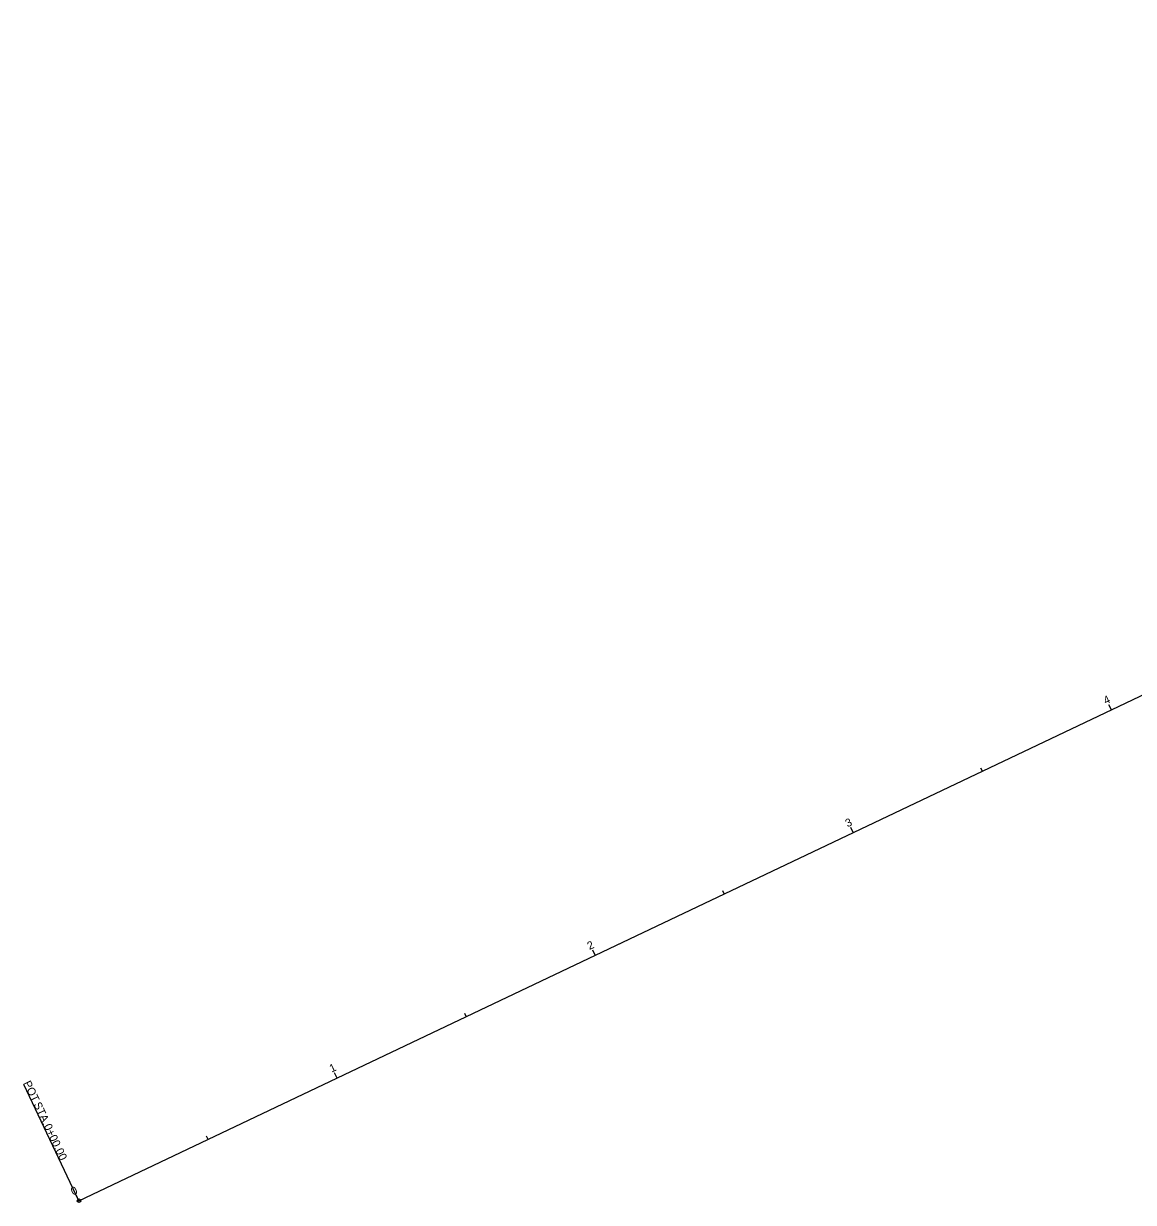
# Model space of a CAD drawing. Extents: x 219353 to 221640, y 361458 to 364236.
# Drawn here: x 219352.5 to 219740.9, y 361639.9 to 362052.3 of the extents above; entities that cross this region are included whole.
import ezdxf

# ---------------------------------------------------------------- set-up
doc = ezdxf.new("R2010")
doc.units = 0
for name, color, linetype in [('DR_X_Cells', 7, 'Continuous'), ('DT_X_Contour_Major', 7, 'Continuous'), ('SC_ProfileRun2', 7, 'Continuous'), ('SC_ProfileRun3', 7, 'Continuous'), ('UT_X_Sanitary_Cells', 7, 'Continuous')]:
    doc.layers.add(name, color=color, linetype=linetype)

msp = doc.modelspace()

# ---------------------------------------------------------------- linework, layer by layer
at = {"layer": 'DR_X_Cells'}
msp.add_line((219371.89, 361640.54), (219352.58, 361681.19), dxfattribs=at)
msp.add_circle((219371.89, 361640.54), 0.6, dxfattribs=at)
at = {"layer": 'DT_X_Contour_Major'}
msp.add_line((219371.89, 361640.54), (220238.34, 362052.3), dxfattribs=at)
msp.add_line((219371.89, 361640.54), (220238.34, 362052.3), dxfattribs=at)
at = {"layer": 'SC_ProfileRun2'}
msp.add_line((219371.89, 361640.54), (219352.58, 361681.19), dxfattribs=at)
msp.add_circle((219371.89, 361640.54), 0.6, dxfattribs=at)
at = {"layer": 'SC_ProfileRun3'}
for p, q in [((219733.17, 361812.23), (219732.66, 361813.32)), ((219642.85, 361769.31), (219642.34, 361770.39)), ((219552.53, 361726.39), (219552.02, 361727.47)), ((219462.21, 361683.46), (219461.7, 361684.55)), ((219371.89, 361640.54), (219371.04, 361642.35))]:
    msp.add_line(p, q, dxfattribs=at)
at = {"layer": 'UT_X_Sanitary_Cells'}
for p, q in [((219733.17, 361812.23), (219732.31, 361814.04)), ((219688.01, 361790.77), (219687.5, 361791.85)), ((219642.85, 361769.31), (219641.99, 361771.12)), ((219597.69, 361747.85), (219597.18, 361748.93)), ((219552.53, 361726.39), (219551.68, 361728.19)), ((219507.37, 361704.93), (219506.86, 361706.01)), ((219462.21, 361683.46), (219461.36, 361685.27)), ((219417.05, 361662), (219416.54, 361663.09)), ((219371.89, 361640.54), (219371.04, 361642.35))]:
    msp.add_line(p, q, dxfattribs=at)

# ---------------------------------------------------------------- texts
at = {"layer": 'DR_X_Cells'}
for s, p in [('POT', (219352.37, 361681.71)), (' STA. ', (219355.47, 361675.21)), ('0+00.00', (219359.52, 361666.67))]:
    msp.add_text(s, height=2.8, rotation=295.4184, dxfattribs=at).set_placement(p)
at = {"layer": 'SC_ProfileRun2'}
for s, p in [('POT', (219352.37, 361681.71)), (' STA. ', (219355.47, 361675.21)), ('0+00.00', (219359.52, 361666.67))]:
    msp.add_text(s, height=2.8, rotation=295.4184, dxfattribs=at).set_placement(p)
at = {"layer": 'SC_ProfileRun3'}
msp.add_text('0', height=2.8, rotation=25.4184, dxfattribs=at).set_placement((219369.82, 361642.32))
at = {"layer": 'UT_X_Sanitary_Cells'}
for s, p in [('4', (219731.16, 361814.04)), ('3', (219640.84, 361771.12)), ('2', (219550.52, 361728.2)), ('1', (219460.31, 361685.33)), ('0', (219369.82, 361642.32))]:
    msp.add_text(s, height=2.8, rotation=25.4184, dxfattribs=at).set_placement(p)

doc.saveas('drawing.dxf')
